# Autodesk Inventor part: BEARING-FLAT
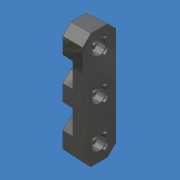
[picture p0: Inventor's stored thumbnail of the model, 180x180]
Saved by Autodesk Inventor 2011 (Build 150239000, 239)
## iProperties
Created: 2007-10
Part Number: BEARING-FLAT
Document SubType Name: Modeling
Material: Delrin, Black
Density: 1.425 g/cm^3
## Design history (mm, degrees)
feature "Base1"
body "Solid1"
